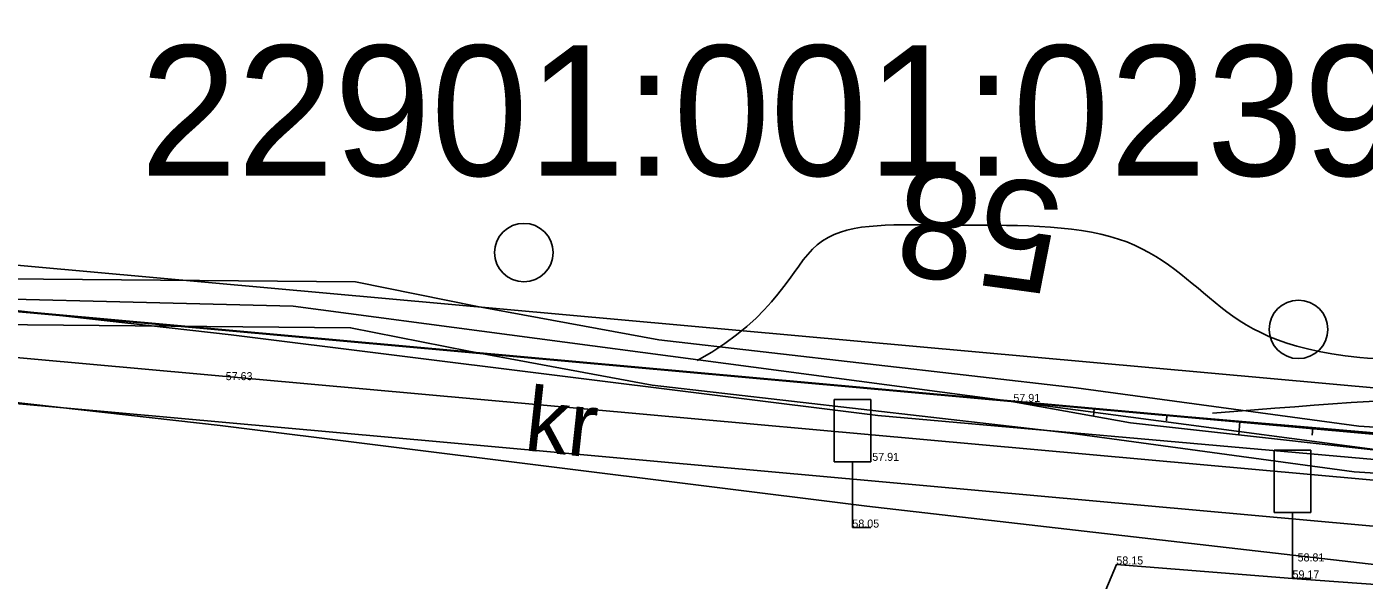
# Model space of a CAD drawing. Extents: x 700746 to 706058, y 6570320 to 6580460.
# Drawn here: x 702893.2 to 702951.6, y 6577451 to 6577475.2 of the extents above; entities that cross this region are included whole.
import ezdxf

# ---------------------------------------------------------------- set-up
doc = ezdxf.new("R2010")
doc.units = 0
for name, color, linetype in [('HALJASTUS', 7, 'Continuous'), ('HORISONTAAL-EH2000', 7, 'Continuous'), ('illumineerimisjooned', 7, 'Continuous'), ('Kaitsevöönd', 7, 'Continuous'), ('kataster', 7, 'Continuous'), ('Kataster tekst', 7, 'Continuous'), ('KPOHULIIN', 7, 'Continuous'), ('LIIKLUS', 7, 'Continuous'), ('MOOTKORG-EH2000', 7, 'Continuous'), ('mäeeraldis', 7, 'Continuous'), ('mäeeraldise teenindusmaa', 7, 'Continuous'), ('Plokid', 7, 'Continuous'), ('RELJEEF', 7, 'Continuous'), ('TEE', 7, 'Continuous'), ('VWX2_MV_PLOKK', 7, 'Continuous')]:
    doc.layers.add(name, color=color, linetype=linetype)

msp = doc.modelspace()

# ---------------------------------------------------------------- linework, layer by layer
at = {"layer": 'HALJASTUS'}
for centre in [(702914.902, 6577465.302), (702914.902, 6577465.302), (702948.766, 6577461.947), (702948.766, 6577461.947)]:
    msp.add_circle(centre, 1.28, dxfattribs=at)
at = {"layer": 'HORISONTAAL-EH2000'}
for points in [[(702922.477, 6577460.579), (702926.07, 6577462.57), (702927.032, 6577466.744), (702932.645, 6577466.408), (702941.38, 6577466.667), (702944.982, 6577462.991), (702949.414, 6577460.102), (702966.044, 6577460.934), (702968.524, 6577468.522), (702969.39, 6577480.857), (702965.363, 6577489.898), (702965.1, 6577495.323), (702964.472, 6577496.896), (702966.698, 6577500.036), (702968.166, 6577501.94), (702967.969, 6577503.592), (702967.904, 6577503.919)], [(702945.015, 6577458.278), (702955.029, 6577459.116), (702967.813, 6577459.534), (702972.092, 6577460.118), (702972.091, 6577462.286), (702971.11, 6577467.773), (702973.263, 6577471.134), (702974.775, 6577480.252), (702973.921, 6577488.071), (702973.739, 6577492.968), (702976.128, 6577494.406), (702985.965, 6577494.675), (702992.079, 6577496.335), (702989.442, 6577499.441), (702982.447, 6577500.757), (702983.152, 6577502.241), (702985.262, 6577503.44), (702986.008, 6577503.88)]]:
    msp.add_open_spline(points, degree=3, dxfattribs=at)
at = {"layer": 'illumineerimisjooned'}
for points in [[(703281.213, 6577072.058), (703170.159, 6577171.774), (703168.929, 6577173.195), (703127.168, 6577443.561), (702857.567, 6577467.93), (702860.381, 6577440.007), (702861.165, 6577378.171)], [(702863.784, 6577290.018), (702865.214, 6577375.332), (702864.385, 6577440.164), (702864.379, 6577440.224), (702864.379, 6577440.233), (702862.035, 6577463.486), (703118.822, 6577440.287), (703124.016, 6577437.389), (703150.875, 6577263.871), (703165.133, 6577171.562), (703165.173, 6577171.504), (703167.053, 6577159.433)]]:
    msp.add_lwpolyline(points, dxfattribs=at)
at = {"layer": 'Kaitsevöönd'}
for points in [[(702794.95, 6577364.777), (702818.389, 6577375.72), (702828.735, 6577379.058), (702838.212, 6577380.843), (702838.52, 6577388.149), (702852.487, 6577387.705), (702858.963, 6577390.846), (702860.787, 6577393.4), (702861.569, 6577397.509), (702862.199, 6577442.954), (702865.165, 6577459.616), (702869.066, 6577462.299), (702883.648, 6577464.23), (702907.533, 6577464.018), (702912.866, 6577462.951), (702920.802, 6577461.489), (702939.041, 6577459.391), (702951.401, 6577457.715), (702964.6, 6577456.876), (702977.299, 6577455.818), (702986.331, 6577453.296), (703006.151, 6577451.418), (703028.404, 6577450.788), (703068.332, 6577446.793)], [(703068.332, 6577446.793), (703028.404, 6577450.788), (703006.151, 6577451.418), (702986.331, 6577453.296), (702977.299, 6577455.818), (702964.6, 6577456.876), (702951.401, 6577457.715), (702939.041, 6577459.391), (702920.802, 6577461.489), (702912.866, 6577462.951), (702907.533, 6577464.018), (702883.648, 6577464.23), (702869.066, 6577462.299), (702865.165, 6577459.616), (702862.199, 6577442.954), (702861.569, 6577397.509), (702860.787, 6577393.4), (702858.963, 6577390.846), (702852.487, 6577387.705), (702838.52, 6577388.149), (702838.212, 6577380.843), (702828.735, 6577379.058), (702818.389, 6577375.72), (702794.95, 6577364.777)], [(703068.116, 6577444.805), (703028.276, 6577448.79), (703006.028, 6577449.42), (702985.964, 6577451.322), (702976.944, 6577453.84), (702964.453, 6577454.882), (702951.203, 6577455.723), (702938.792, 6577457.407), (702920.506, 6577459.51), (702912.489, 6577460.987), (702907.326, 6577462.02), (702883.771, 6577462.229), (702869.804, 6577460.379), (702866.988, 6577458.442), (702864.196, 6577442.764), (702863.567, 6577397.307), (702862.67, 6577392.595), (702860.295, 6577389.269), (702852.917, 6577385.69), (702840.435, 6577386.087), (702840.143, 6577379.172), (702829.229, 6577377.116), (702819.122, 6577373.855), (702795.781, 6577362.957)], [(702795.781, 6577362.957), (702819.122, 6577373.855), (702829.229, 6577377.116), (702840.143, 6577379.172), (702840.435, 6577386.087), (702852.917, 6577385.69), (702860.295, 6577389.269), (702862.67, 6577392.595), (702863.567, 6577397.307), (702864.196, 6577442.764), (702866.988, 6577458.442), (702869.804, 6577460.379), (702883.771, 6577462.229), (702907.326, 6577462.02), (702912.489, 6577460.987), (702920.506, 6577459.51), (702938.792, 6577457.407), (702951.203, 6577455.723), (702964.453, 6577454.882), (702976.944, 6577453.84), (702985.964, 6577451.322), (703006.028, 6577449.42), (703028.276, 6577448.79), (703068.116, 6577444.805)]]:
    msp.add_lwpolyline(points, dxfattribs=at)
at = {"layer": 'kataster'}
msp.add_lwpolyline([(703360.09, 6576531.99), (703277.36, 6577072.83), (703167.04, 6577172.32), (703125.43, 6577441.71), (702859.8, 6577465.72), (702862.38, 6577440.12), (702863.2, 6577375.41), (702851.4, 6577379.23), (702839.86, 6577381.59), (702831.19, 6577380.43), (702820.1, 6577376.69), (702754.28, 6577347.92), (702741.83, 6577344.92), (702732.67, 6577344.2), (702712.5, 6577346.91), (702704.73, 6577347.96), (702701.8, 6577345.85), (702700.78, 6577341.43), (702712.4, 6577226.51), (702651.69, 6577159.42), (702595.69, 6577121.68), (702628.71, 6576895.25), (702720.42, 6576547.28)], dxfattribs=at)
msp.add_lwpolyline([(702859.8, 6577465.72), (703125.43, 6577441.71), (703167.04, 6577172.32), (703141.54, 6577201.64), (703129.16, 6577218.59), (703119.31, 6577233.95), (703096.08, 6577280.59), (703057.1, 6577329.85), (703041.25, 6577339.7), (703019.19, 6577342.06), (703005.04, 6577344.66), (702961.68, 6577364.05), (702944.77, 6577367.92), (702900.72, 6577367.74), (702878.06, 6577370.59), (702863.2, 6577375.41), (702862.38, 6577440.12)], close=True, dxfattribs=at)
at = {"layer": 'KPOHULIIN'}
msp.add_lwpolyline([(703039.136, 6577448.892), (703002.934, 6577450.534), (702965.942, 6577455.537), (702952.102, 6577456.696), (702904.814, 6577462.955), (702884.959, 6577463.451), (702869.844, 6577461.464), (702865.651, 6577459.091), (702863.169, 6577441.596), (702862.294, 6577397.954), (702861.529, 6577393.511), (702859.8, 6577390.103), (702852.209, 6577386.673), (702839.708, 6577387.157), (702839.039, 6577386.59), (702839.027, 6577380.043), (702829, 6577378.2), (702826.581, 6577377.417), (702819.524, 6577374.929), (702807.768, 6577369.321)], dxfattribs=at)
at = {"layer": 'LIIKLUS'}
for p, q in [((702928.463, 6577458.88), (702928.463, 6577456.16)), ((702930.063, 6577458.88), (702928.463, 6577458.88)), ((702928.463, 6577458.88), (702928.463, 6577456.16)), ((702930.063, 6577458.88), (702928.463, 6577458.88)), ((702928.463, 6577458.88), (702928.463, 6577456.16)), ((702930.063, 6577458.88), (702928.463, 6577458.88)), ((702930.063, 6577458.88), (702930.063, 6577456.16)), ((702930.063, 6577458.88), (702930.063, 6577456.16)), ((702930.063, 6577458.88), (702930.063, 6577456.16)), ((702947.709, 6577456.658), (702947.709, 6577453.938)), ((702949.309, 6577456.658), (702947.709, 6577456.658)), ((702947.709, 6577456.658), (702947.709, 6577453.938)), ((702949.309, 6577456.658), (702947.709, 6577456.658)), ((702947.709, 6577456.658), (702947.709, 6577453.938)), ((702949.309, 6577456.658), (702947.709, 6577456.658)), ((702949.309, 6577456.658), (702949.309, 6577453.938)), ((702949.309, 6577456.658), (702949.309, 6577453.938)), ((702949.309, 6577456.658), (702949.309, 6577453.938)), ((702930.063, 6577456.16), (702928.463, 6577456.16)), ((702930.063, 6577456.16), (702928.463, 6577456.16)), ((702930.063, 6577456.16), (702928.463, 6577456.16)), ((702929.263, 6577456.16), (702929.263, 6577453.28)), ((702929.263, 6577456.16), (702929.263, 6577453.28)), ((702929.263, 6577456.16), (702929.263, 6577453.28)), ((702949.309, 6577453.938), (702947.709, 6577453.938)), ((702949.309, 6577453.938), (702947.709, 6577453.938)), ((702949.309, 6577453.938), (702947.709, 6577453.938)), ((702948.509, 6577453.938), (702948.509, 6577451.058)), ((702948.509, 6577453.938), (702948.509, 6577451.058)), ((702948.509, 6577453.938), (702948.509, 6577451.058)), ((702930.063, 6577453.28), (702929.263, 6577453.28)), ((702930.063, 6577453.28), (702929.263, 6577453.28)), ((702930.063, 6577453.28), (702929.263, 6577453.28)), ((702949.309, 6577451.058), (702948.509, 6577451.058)), ((702949.309, 6577451.058), (702948.509, 6577451.058)), ((702949.309, 6577451.058), (702948.509, 6577451.058))]:
    msp.add_line(p, q, dxfattribs=at)
at = {"layer": 'mäeeraldis'}
msp.add_lwpolyline([(702859.802, 6577465.696), (703119.425, 6577442.241), (703125.486, 6577438.859), (703125.878, 6577438.438), (703152.852, 6577264.176), (703167.04, 6577172.32), (703167.079, 6577172.263), (703170.22, 6577152.098), (703089.87, 6577211.79), (702861.725, 6577286.484), (702863.214, 6577375.336), (702862.386, 6577440.049), (702862.38, 6577440.109), (702862.38, 6577440.12), (702859.802, 6577465.696)], dxfattribs=at)
at = {"layer": 'mäeeraldise teenindusmaa'}
msp.add_lwpolyline([(702859.8, 6577465.72), (703125.43, 6577441.71), (703167.04, 6577172.32), (703168.73, 6577170.37), (703277.36, 6577072.83), (703231.53, 6577106.55), (703089.87, 6577211.79), (702713.81, 6577334.91), (702712.5, 6577346.91), (702732.67, 6577344.2), (702741.83, 6577344.92), (702754.28, 6577347.92), (702820.1, 6577376.69), (702831.19, 6577380.43), (702839.86, 6577381.59), (702851.4, 6577379.23), (702863.2, 6577375.41), (702862.38, 6577440.12), (702859.8, 6577465.72)], dxfattribs=at)
at = {"layer": 'Plokid'}
msp.add_lwpolyline([(703043.339, 6577445.098), (703121.898, 6577438.001), (703148.899, 6577263.565), (703163.227, 6577170.805), (703163.267, 6577170.746), (703164.325, 6577163.951), (703092.665, 6577217.188), (702865.809, 6577291.46), (702867.214, 6577375.329), (702866.384, 6577440.28), (702866.378, 6577440.34), (702866.377, 6577440.346), (702864.268, 6577461.276), (703043.339, 6577445.098)], dxfattribs=at)
at = {"layer": 'RELJEEF'}
for p, q in [((702936.303, 6577458.773), (702936.303, 6577458.773)), ((702936.641, 6577458.729), (702936.642, 6577458.744)), ((702939.83, 6577458.471), (702939.802, 6577458.148)), ((702942.997, 6577457.942), (702943.018, 6577458.198)), ((702946.207, 6577457.925), (702946.156, 6577457.333)), ((702949.366, 6577457.316), (702949.395, 6577457.652))]:
    msp.add_line(p, q, dxfattribs=at)
for points in [[(703039.79, 6577447.54), (703025.22, 6577449.6), (703016.03, 6577449.1), (703007.61, 6577449.54), (702997.49, 6577450.76), (702985.4, 6577452.59), (702970.52, 6577454.63), (702941.429, 6577457.857), (702936.303, 6577458.773)], [(703039.79, 6577447.54), (703039.29, 6577448.71), (703033.05, 6577451.71), (703022.02, 6577451.75), (703017.13, 6577450.98), (703014.4, 6577452.56), (703011.98, 6577452.9), (703009.76, 6577452.8), (703003.16, 6577454.37), (702997.04, 6577453.77), (702993.32, 6577454.7), (702983.71, 6577454.97), (702972.76, 6577455.65), (702936.303, 6577458.773)], [(703109.46, 6577431.896), (703109.656, 6577434.759), (703101.214, 6577436.715), (703085.509, 6577439.638), (703069.305, 6577441.281), (703037.55, 6577444.252), (703013.327, 6577445.875), (702998.889, 6577446.952), (702979.072, 6577448.832), (702948.509, 6577451.058), (702940.805, 6577451.666), (702938.45, 6577446.059), (702946.65, 6577438.44), (702961.408, 6577434.473), (702975.034, 6577431.125), (702985.22, 6577430.254), (702985.226, 6577430.27)]]:
    msp.add_lwpolyline(points, dxfattribs=at)
at = {"layer": 'TEE'}
for points in [[(702854.295, 6577385.64), (702860.479, 6577389.575), (702862.441, 6577395.052), (702863.39, 6577422.051), (702863.228, 6577439.724), (702864.831, 6577448.811), (702868.15, 6577454.02), (702882.063, 6577461.794), (702891.371, 6577462.918), (702902.098, 6577461.712), (702930.372, 6577458.183), (702970.52, 6577454.63), (702979.741, 6577452.7), (703007.61, 6577449.54), (703016.03, 6577449.1), (703039.79, 6577447.54), (703064.11, 6577445.63), (703091.649, 6577443.036), (703115.431, 6577437.527), (703121.504, 6577429.638), (703126.034, 6577420.563), (703128.417, 6577398.523), (703132.082, 6577374.622), (703133.755, 6577354.122)], [(702862.217, 6577386.504), (702865.634, 6577388.714), (702866.439, 6577394.912), (702867.391, 6577421.999), (702867.231, 6577439.393), (702868.631, 6577447.333), (702870.981, 6577451.02), (702883.325, 6577457.917), (702891.388, 6577458.891), (702901.627, 6577457.74), (702929.896, 6577454.211), (702966.011, 6577450.063), (702979.36, 6577448.718), (703005.469, 6577446.357), (703022.241, 6577445.328), (703043.653, 6577443.823), (703061.336, 6577442.089), (703090.993, 6577439.082), (703113.134, 6577433.953), (703118.098, 6577427.505), (703122.134, 6577419.419), (703124.449, 6577398.005), (703128.111, 6577374.126), (703130.043, 6577354.145)]]:
    msp.add_lwpolyline(points, dxfattribs=at)
at = {"layer": 'VWX2_MV_PLOKK'}
for points in [[(702671.98, 6577568.29), (702779.72, 6577521), (702911.62, 6577488.86), (703121.85, 6577464.43), (703125.37, 6577441.7), (702859.74, 6577465.7), (702862.39, 6577440.05), (702863.21, 6577375.33), (702861.72, 6577286.46), (702849.88, 6577229.56), (702759.17, 6577231.22), (702698.87, 6577370.58)], [(702671.98, 6577568.29), (702779.72, 6577521), (702911.62, 6577488.86), (703121.85, 6577464.43), (703125.37, 6577441.7), (702859.74, 6577465.7), (702862.39, 6577440.05), (702863.21, 6577375.33), (702861.72, 6577286.46), (702849.88, 6577229.56), (702759.17, 6577231.22), (702698.87, 6577370.58)], [(702859.74, 6577465.7), (703125.37, 6577441.7), (703167.08, 6577172.26), (703170.22, 6577152.07), (703089.79, 6577211.82), (702861.72, 6577286.46), (702863.21, 6577375.33), (702862.39, 6577440.05)], [(702859.74, 6577465.7), (703125.37, 6577441.7), (703167.08, 6577172.26), (703170.22, 6577152.07), (703089.79, 6577211.82), (702861.72, 6577286.46), (702863.21, 6577375.33), (702862.39, 6577440.05)]]:
    msp.add_lwpolyline(points, close=True, dxfattribs=at)

# ---------------------------------------------------------------- texts
at = {"layer": 'HORISONTAAL-EH2000'}
msp.add_text('58', height=4.8, rotation=172.17807, dxfattribs=at).set_placement((702938.638, 6577468.204))
at = {"layer": 'Kataster tekst'}
msp.add_text('22901:001:0239', height=5.7, dxfattribs=at).set_placement((702898.121, 6577468.661))
at = {"layer": 'MOOTKORG-EH2000'}
for s, p in [('57.63', (702901.863, 6577459.726)), ('57.91', (702936.303, 6577458.773)), ('57.91', (702930.134, 6577456.197)), ('58.05', (702929.263, 6577453.28)), ('58.15', (702940.805, 6577451.666)), ('58.81', (702948.73, 6577451.799)), ('59.17', (702948.509, 6577451.058))]:
    msp.add_text(s, height=0.35, dxfattribs=at).set_placement(p)
at = {"layer": 'TEE'}
msp.add_text('kr', height=2.8, rotation=353.81671, dxfattribs=at).set_placement((702914.863, 6577456.665))

doc.saveas('drawing.dxf')
